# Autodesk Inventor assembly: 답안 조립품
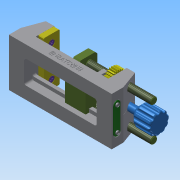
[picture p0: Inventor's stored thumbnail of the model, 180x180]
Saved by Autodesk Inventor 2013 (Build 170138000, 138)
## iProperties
Created: 2017-04
Part Number: 답안 조립품
Document SubType Name: Assembly
Designer: 나래
Mass: 1270 g
Surface Area: 784.418 cm^2
Volume: 280.832 cm^3
Density: 4.52228 g/cm^3
Author: 나래
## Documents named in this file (10)
- C:\Users\나래\Desktop\370408V1020\답안 조립품.iam
- C:\Users\나래\Desktop\370408V1020\바이스본체 A.ipt
- C:\Users\나래\Desktop\370408V1020\고정 플레이트.ipt
- C:\Users\나래\Desktop\370408V1020\바이스본체 B.ipt
- C:\Users\나래\Desktop\370408V1020\스퍼기어.ipt
- C:\Users\나래\Desktop\370408V1020\슬라이딩 부품.ipt
- C:\Users\나래\Desktop\370408V1020\십자오목머리나사 M3.ipt
- C:\Users\나래\Desktop\370408V1020\십자오목머리나사 M4.ipt
- C:\Users\나래\Desktop\370408V1020\지지대.ipt
- C:\Users\나래\Desktop\370408V1020\핸들.ipt
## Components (3 placed, 2 different names)
1. 고정 플레이트:1
2. 핸들:1 — 플러쉬:2, 각도:1
3. 고정 플레이트:2
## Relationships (2: Flush 1, Angle 1)
- 플러쉬:2 [Flush]: 핸들:1
- 각도:1 [Angle]: 핸들:1
